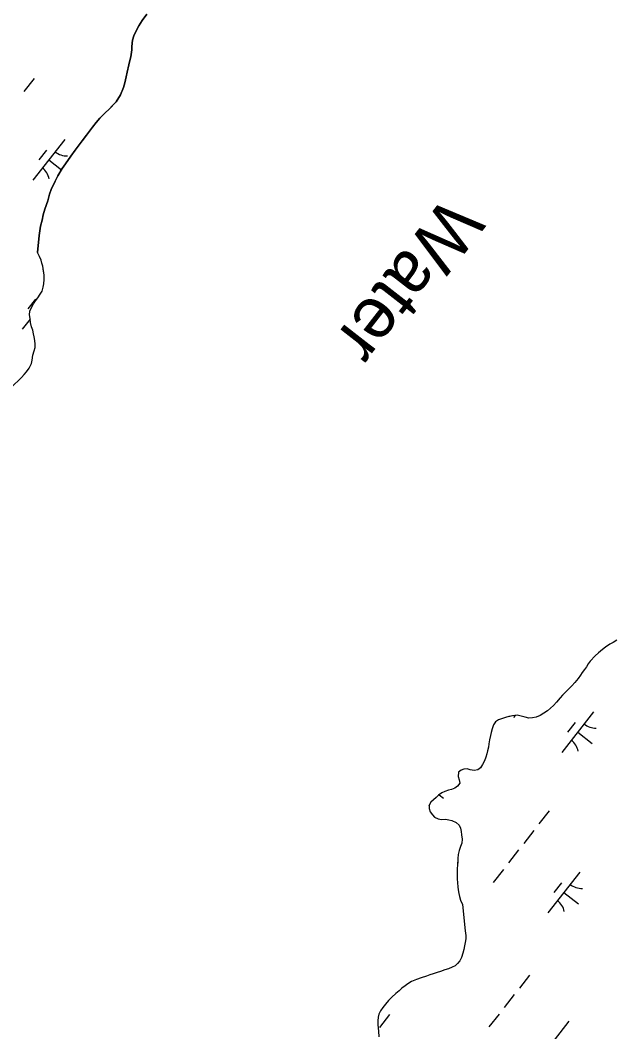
# Model space of a CAD drawing. Extents: x 3896831 to 3918110, y 171006 to 193349.
# Drawn here: x 3911519 to 3912098, y 179895 to 180876 of the extents above; entities that cross this region are included whole.
import ezdxf

# ---------------------------------------------------------------- set-up
doc = ezdxf.new("R2010")
doc.units = 0
for name, color, linetype in [('V-RIVR-IDEN', 7, 'Continuous'), ('V-TOPO-SHOR', 7, 'Continuous'), ('V-WETL-SWMP', 7, 'Continuous')]:
    doc.layers.add(name, color=color, linetype=linetype)

msp = doc.modelspace()

# ---------------------------------------------------------------- linework, layer by layer
at = {"layer": 'V-TOPO-SHOR'}
for points in [[(3911642.32, 180881.66), (3911637.81, 180875.42), (3911634.59, 180870.5), (3911631.06, 180864.27)], [(3911631.06, 180864.27), (3911629.46, 180860.68), (3911628.2, 180856.42), (3911627.6, 180850.22), (3911627.63, 180846.96), (3911626.7, 180840.43), (3911625.76, 180836.84), (3911624.82, 180832.59), (3911623.25, 180825.4), (3911621.99, 180820.83), (3911620.73, 180814.95), (3911619.47, 180810.7), (3911616.6, 180803.5), (3911612.42, 180796.61), (3911609.19, 180793.32), (3911605.31, 180789.38), (3911602.07, 180786.41), (3911596.58, 180780.82), (3911593.03, 180776.55), (3911589.48, 180771.96), (3911583.68, 180764.4), (3911579.49, 180758.82), (3911572.72, 180749.63), (3911568.53, 180744.05), (3911563.38, 180736.51), (3911560.16, 180731.92), (3911555.98, 180725.03), (3911553.1, 180719.79), (3911549.25, 180711.6), (3911547.66, 180707.02), (3911546.09, 180700.49), (3911543.23, 180692.64), (3911541.65, 180687.08), (3911540.71, 180681.85), (3911539.13, 180675.97), (3911537.58, 180667.15), (3911536.99, 180660.3), (3911536.1, 180650.83), (3911536.03, 180650.38)], [(3911523.18, 180532.04), (3911525.38, 180534.79), (3911527.99, 180538.47), (3911530.35, 180542.95), (3911530.95, 180546.14), (3911531.72, 180550.92), (3911533.01, 180555.3), (3911533.74, 180558.48), (3911533.81, 180561.68), (3911533.48, 180565.15), (3911532.89, 180568.63), (3911532.29, 180571.58), (3911531.43, 180575.2), (3911530.3, 180578.42), (3911529.45, 180582.57), (3911528.87, 180586.58), (3911528.41, 180590.06), (3911528.62, 180593.52), (3911530.29, 180597.09), (3911532.37, 180600.77), (3911534.3, 180603.8), (3911536.49, 180606.69), (3911538.7, 180610.24), (3911540.49, 180613.01), (3911541.64, 180616.98), (3911542.38, 180620.17), (3911542.47, 180624.43), (3911542.68, 180628.42), (3911541.97, 180632.44), (3911541.14, 180637.12), (3911540.26, 180640.07), (3911539.52, 180643.02), (3911538.14, 180646.65), (3911536.03, 180650.38)], [(3911517.6, 180526.29), (3911520.73, 180529.29), (3911523.18, 180532.04)], [(3912098.29, 180274.6), (3912094.63, 180272.27), (3912091.38, 180270.47), (3912087.31, 180267.61), (3912084.46, 180265.4), (3912080.37, 180262.14), (3912077.37, 180259.4), (3912072.45, 180254.28), (3912070.52, 180251.65), (3912068.72, 180248.74), (3912066.79, 180246.11), (3912064.73, 180243.08), (3912062.94, 180240.57), (3912060.73, 180237.28), (3912057.44, 180233.47), (3912054.42, 180230.06), (3912051.82, 180227.3), (3912048.54, 180224.03), (3912045.67, 180221.15), (3912043.34, 180218.52), (3912039.65, 180214.32), (3912036.77, 180211.3), (3912033.91, 180208.55), (3912030.91, 180205.81), (3912027.25, 180203.61), (3912023.73, 180201.55), (3912020.08, 180199.88), (3912016.45, 180199.02), (3912012.7, 180198.84), (3912009.24, 180199.71), (3912005.39, 180200.86), (3912001.53, 180201.61), (3911997.11, 180201.17), (3911993.34, 180200.32), (3911990.12, 180199.58), (3911986.35, 180198.32), (3911983.52, 180197.31), (3911980.53, 180195.37), (3911978.73, 180192.47), (3911977.18, 180188.35), (3911976.3, 180185.03), (3911975.7, 180181.96), (3911974.81, 180177.84), (3911974.06, 180173.97), (3911973.59, 180170.64), (3911972.85, 180167.31), (3911972.25, 180164.25), (3911971.25, 180160.93), (3911969.84, 180157.48), (3911968.02, 180153.91), (3911966.08, 180150.6), (3911963.23, 180148.79), (3911959.87, 180148.06), (3911956.01, 180148.68), (3911953.09, 180149.67), (3911949.88, 180149.47), (3911947.04, 180148.33), (3911944.46, 180146.38)], [(3911944.46, 180146.38), (3911944.37, 180142.37), (3911945.11, 180139.14), (3911945.98, 180135.91), (3911943.77, 180132.75), (3911941.19, 180130.8), (3911937.82, 180129.67), (3911934.86, 180128.93), (3911931.36, 180127.66), (3911928.52, 180126.39), (3911925.27, 180124.18), (3911922.81, 180121.83), (3911920.49, 180119.74), (3911917.77, 180117.52), (3911916.24, 180114.61), (3911916.17, 180111.13), (3911917.17, 180107.9), (3911919.38, 180105.05), (3911921.47, 180102.73), (3911924.79, 180101.32), (3911928.25, 180100.71), (3911932.13, 180100.76), (3911935.2, 180100.3), (3911938.26, 180099.56), (3911942.36, 180097.74), (3911945.25, 180095), (3911946.39, 180092.04), (3911947.12, 180088.81), (3911947.59, 180085.59), (3911948.04, 180081.57), (3911947.69, 180077.57), (3911946.55, 180074.25), (3911945.27, 180070.53), (3911944.38, 180066.54), (3911943.9, 180062.67), (3911943.83, 180059.59), (3911943.77, 180056.38), (3911943.29, 180053.05), (3911943.23, 180049.84), (3911943.28, 180046.23), (3911943.35, 180043.02), (3911943.54, 180039.27), (3911944.12, 180035.38), (3911944.33, 180032.3), (3911944.79, 180028.81), (3911945.66, 180025.72), (3911946.66, 180022.22), (3911948.44, 180018.04), (3911950.98, 179992.44), (3911951.69, 179988.14), (3911951.75, 179984.93), (3911951.14, 179981.33), (3911950.54, 179978.14), (3911949.8, 179974.54), (3911948.78, 179970.82), (3911947.36, 179966.7), (3911945.82, 179963.52), (3911943.76, 179960.89), (3911941.3, 179958.67), (3911938.6, 179957.26), (3911934.95, 179955.6), (3911931.32, 179954.6), (3911927.01, 179953.22), (3911923.91, 179952.22), (3911920.01, 179950.96), (3911916.65, 179949.96), (3911913.41, 179948.69), (3911908.29, 179946.93), (3911903.71, 179945.29), (3911899.12, 179943.51), (3911895.33, 179941.32), (3911892.75, 179939.37), (3911889.49, 179936.89), (3911886.9, 179934.54), (3911883.89, 179931.66), (3911880.08, 179928.27), (3911876.66, 179924.86), (3911873.65, 179921.45), (3911871.17, 179918.29), (3911868.96, 179914.99), (3911867.43, 179911.81), (3911866.56, 179908.76), (3911866.22, 179905.29), (3911866.41, 179901.8), (3911866.74, 179898.32), (3911867.07, 179895.1), (3911867.37, 179889.88)]]:
    msp.add_lwpolyline(points, dxfattribs=at)
at = {"layer": 'V-WETL-SWMP'}
for p, q in [((3911634.59, 180870.5), (3911637.81, 180875.42)), ((3911637.81, 180875.42), (3911642.32, 180881.66)), ((3911629.46, 180860.68), (3911631.06, 180864.28)), ((3911631.06, 180864.28), (3911634.59, 180870.5)), ((3911627.6, 180850.22), (3911628.2, 180856.42)), ((3911628.2, 180856.42), (3911629.46, 180860.68)), ((3911626.71, 180840.43), (3911627.63, 180846.96)), ((3911627.63, 180846.96), (3911627.6, 180850.22)), ((3911624.82, 180832.59), (3911625.76, 180836.84)), ((3911625.76, 180836.84), (3911626.71, 180840.43)), ((3911621.99, 180820.83), (3911623.25, 180825.4)), ((3911623.25, 180825.4), (3911624.82, 180832.59)), ((3911532.76, 180819.39), (3911522.89, 180806.8)), ((3911619.47, 180810.7), (3911620.73, 180814.95)), ((3911620.73, 180814.95), (3911621.99, 180820.83)), ((3911616.6, 180803.5), (3911619.47, 180810.7)), ((3911605.31, 180789.38), (3911612.42, 180796.61)), ((3911612.42, 180796.61), (3911616.6, 180803.5)), ((3911596.58, 180780.82), (3911602.07, 180786.41)), ((3911602.07, 180786.41), (3911605.31, 180789.38)), ((3911589.48, 180771.96), (3911593.03, 180776.55)), ((3911593.03, 180776.55), (3911596.58, 180780.82)), ((3911579.49, 180758.82), (3911583.68, 180764.4)), ((3911583.68, 180764.4), (3911589.48, 180771.96)), ((3911562.48, 180759.99), (3911531.64, 180720.63)), ((3911572.72, 180749.63), (3911579.49, 180758.82)), ((3911544.69, 180749.79), (3911537.28, 180740.35)), ((3911568.53, 180744.05), (3911572.72, 180749.63)), ((3911547.06, 180740.31), (3911559.39, 180730.64)), ((3911560.16, 180731.92), (3911563.38, 180736.51)), ((3911563.38, 180736.51), (3911568.53, 180744.05)), ((3911555.98, 180725.03), (3911560.16, 180731.92)), ((3911549.25, 180711.6), (3911553.1, 180719.79)), ((3911553.1, 180719.79), (3911555.98, 180725.03)), ((3911546.09, 180700.49), (3911547.67, 180707.02)), ((3911547.67, 180707.02), (3911549.25, 180711.6)), ((3911543.23, 180692.64), (3911546.09, 180700.49)), ((3911540.71, 180681.85), (3911541.65, 180687.08)), ((3911541.65, 180687.08), (3911543.23, 180692.64)), ((3911539.13, 180675.97), (3911540.71, 180681.85)), ((3911536.99, 180660.3), (3911537.58, 180667.15)), ((3911537.58, 180667.15), (3911539.13, 180675.97)), ((3911536.1, 180650.83), (3911536.99, 180660.3)), ((3911536.03, 180650.38), (3911536.1, 180650.83)), ((3911538.14, 180646.65), (3911536.03, 180650.38)), ((3911539.52, 180643.02), (3911538.14, 180646.65)), ((3911540.26, 180640.07), (3911539.52, 180643.02)), ((3911541.13, 180637.12), (3911540.26, 180640.07)), ((3911542.68, 180628.42), (3911541.13, 180637.12)), ((3911542.47, 180624.43), (3911542.68, 180628.42)), ((3911541.64, 180616.98), (3911542.38, 180620.16)), ((3911542.38, 180620.16), (3911542.47, 180624.43)), ((3911536.49, 180606.69), (3911538.7, 180610.24)), ((3911538.7, 180610.24), (3911540.49, 180613.01)), ((3911540.49, 180613.01), (3911541.64, 180616.98)), ((3911534.22, 180605.23), (3911526.81, 180595.79)), ((3911530.29, 180597.09), (3911532.37, 180600.78)), ((3911532.37, 180600.78), (3911534.3, 180603.8)), ((3911534.3, 180603.8), (3911536.49, 180606.69)), ((3911528.41, 180590.06), (3911528.62, 180593.52)), ((3911528.87, 180586.58), (3911528.41, 180590.06)), ((3911528.62, 180593.52), (3911530.29, 180597.09)), ((3911528.95, 180586.01), (3911521.16, 180576.08)), ((3911529.45, 180582.57), (3911528.87, 180586.58)), ((3911530.3, 180578.42), (3911529.45, 180582.57)), ((3911531.43, 180575.2), (3911530.3, 180578.42)), ((3911532.29, 180571.58), (3911531.43, 180575.2)), ((3911532.89, 180568.63), (3911532.29, 180571.58)), ((3911533.48, 180565.15), (3911532.89, 180568.63)), ((3911533.01, 180555.3), (3911533.74, 180558.48)), ((3911533.81, 180561.68), (3911533.48, 180565.15)), ((3911533.74, 180558.48), (3911533.81, 180561.68)), ((3911530.95, 180546.14), (3911531.72, 180550.92)), ((3911531.72, 180550.92), (3911533.01, 180555.3)), ((3911527.99, 180538.47), (3911530.35, 180542.95)), ((3911530.35, 180542.95), (3911530.95, 180546.14)), ((3911510.66, 180519.64), (3911520.73, 180529.29)), ((3911520.73, 180529.29), (3911523.19, 180532.04)), ((3911523.19, 180532.04), (3911525.38, 180534.79)), ((3911525.38, 180534.79), (3911527.99, 180538.47)), ((3912098.29, 180274.6), (3912094.63, 180272.27)), ((3912084.46, 180265.4), (3912080.37, 180262.14)), ((3912087.31, 180267.61), (3912084.46, 180265.4)), ((3912091.38, 180270.47), (3912087.31, 180267.61)), ((3912094.63, 180272.27), (3912091.38, 180270.47)), ((3912072.45, 180254.28), (3912070.52, 180251.65)), ((3912077.37, 180259.4), (3912072.45, 180254.28)), ((3912080.37, 180262.14), (3912077.37, 180259.4)), ((3912066.8, 180246.11), (3912064.73, 180243.08)), ((3912068.72, 180248.74), (3912066.8, 180246.11)), ((3912070.52, 180251.65), (3912068.72, 180248.74)), ((3912060.73, 180237.28), (3912057.44, 180233.47)), ((3912062.93, 180240.57), (3912060.73, 180237.28)), ((3912064.73, 180243.08), (3912062.93, 180240.57)), ((3912051.82, 180227.3), (3912048.54, 180224.03)), ((3912054.42, 180230.06), (3912051.82, 180227.3)), ((3912057.44, 180233.47), (3912054.42, 180230.06)), ((3912043.34, 180218.52), (3912039.64, 180214.32)), ((3912045.67, 180221.15), (3912043.34, 180218.52)), ((3912048.54, 180224.03), (3912045.67, 180221.15)), ((3912030.91, 180205.81), (3912027.25, 180203.61)), ((3912033.91, 180208.55), (3912030.91, 180205.81)), ((3912036.77, 180211.3), (3912033.91, 180208.55)), ((3912039.64, 180214.32), (3912036.77, 180211.3)), ((3911980.53, 180195.37), (3911978.73, 180192.46)), ((3911983.52, 180197.31), (3911980.53, 180195.37)), ((3911986.35, 180198.32), (3911983.52, 180197.31)), ((3911990.12, 180199.58), (3911986.35, 180198.32)), ((3911997.1, 180201.17), (3911990.12, 180199.58)), ((3912001.53, 180201.61), (3911997.1, 180201.17)), ((3911999.55, 180201.42), (3911998, 180199.44)), ((3912005.39, 180200.86), (3912001.53, 180201.61)), ((3912009.24, 180199.71), (3912005.39, 180200.86)), ((3912012.7, 180198.84), (3912009.24, 180199.71)), ((3912016.45, 180199.03), (3912012.7, 180198.84)), ((3912020.08, 180199.88), (3912016.45, 180199.03)), ((3912023.73, 180201.55), (3912020.08, 180199.88)), ((3912027.25, 180203.61), (3912023.73, 180201.55)), ((3912075.68, 180204.99), (3912044.84, 180165.64)), ((3911977.17, 180188.35), (3911976.3, 180185.03)), ((3911978.73, 180192.46), (3911977.17, 180188.35)), ((3912057.89, 180194.8), (3912050.49, 180185.35)), ((3911974.81, 180177.84), (3911974.06, 180173.97)), ((3911975.7, 180181.96), (3911974.81, 180177.84)), ((3911976.3, 180185.03), (3911975.7, 180181.96)), ((3912060.26, 180185.32), (3912074.43, 180174.21)), ((3911972.85, 180167.31), (3911972.25, 180164.25)), ((3911973.59, 180170.64), (3911972.85, 180167.31)), ((3911974.06, 180173.97), (3911973.59, 180170.64)), ((3911969.84, 180157.48), (3911968.02, 180153.91)), ((3911971.25, 180160.93), (3911969.84, 180157.48)), ((3911972.25, 180164.25), (3911971.25, 180160.93)), ((3911944.46, 180146.38), (3911944.37, 180142.37)), ((3911947.04, 180148.33), (3911944.46, 180146.38)), ((3911949.87, 180149.47), (3911947.04, 180148.33)), ((3911953.09, 180149.67), (3911949.87, 180149.47)), ((3911956.01, 180148.68), (3911953.09, 180149.67)), ((3911959.87, 180148.06), (3911956.01, 180148.68)), ((3911963.23, 180148.79), (3911959.87, 180148.06)), ((3911966.08, 180150.6), (3911963.23, 180148.79)), ((3911968.02, 180153.91), (3911966.08, 180150.6)), ((3911944.37, 180142.37), (3911945.11, 180139.14)), ((3911945.11, 180139.14), (3911945.98, 180135.91)), ((3911931.36, 180127.66), (3911928.52, 180126.39)), ((3911934.86, 180128.93), (3911931.36, 180127.66)), ((3911937.82, 180129.67), (3911934.86, 180128.93)), ((3911941.19, 180130.8), (3911937.82, 180129.67)), ((3911943.77, 180132.75), (3911941.19, 180130.8)), ((3911945.98, 180135.91), (3911943.77, 180132.75)), ((3911917.77, 180117.52), (3911916.24, 180114.61)), ((3911920.49, 180119.73), (3911917.77, 180117.52)), ((3911922.81, 180121.83), (3911920.49, 180119.73)), ((3911925.27, 180124.18), (3911922.81, 180121.83)), ((3911928.52, 180126.39), (3911925.27, 180124.18)), ((3911925.85, 180124.58), (3911930.09, 180121.25)), ((3911916.24, 180114.61), (3911916.17, 180111.13)), ((3911916.17, 180111.13), (3911917.17, 180107.9)), ((3911917.17, 180107.9), (3911919.38, 180105.05)), ((3912032.55, 180108.83), (3912022.68, 180096.24)), ((3911919.38, 180105.05), (3911921.47, 180102.73)), ((3911921.47, 180102.73), (3911924.79, 180101.32)), ((3911924.79, 180101.32), (3911928.25, 180100.71)), ((3911928.25, 180100.71), (3911932.13, 180100.76)), ((3911932.13, 180100.76), (3911935.2, 180100.3)), ((3911935.2, 180100.3), (3911938.26, 180099.57)), ((3911938.26, 180099.57), (3911942.36, 180097.74)), ((3911942.36, 180097.74), (3911945.25, 180095)), ((3911945.25, 180095), (3911946.39, 180092.04)), ((3911946.39, 180092.04), (3911947.12, 180088.81)), ((3911947.12, 180088.81), (3911947.59, 180085.59)), ((3912017.74, 180089.94), (3912007.87, 180077.35)), ((3911947.59, 180085.59), (3911948.04, 180081.57)), ((3911948.04, 180081.57), (3911947.69, 180077.57)), ((3911945.27, 180070.53), (3911944.38, 180066.54)), ((3911946.55, 180074.25), (3911945.27, 180070.53)), ((3911947.69, 180077.57), (3911946.55, 180074.25)), ((3912002.94, 180071.05), (3911993.07, 180058.46)), ((3911943.9, 180062.67), (3911943.77, 180056.38)), ((3911944.38, 180066.54), (3911943.9, 180062.67)), ((3911943.29, 180053.05), (3911943.23, 180049.84)), ((3911943.23, 180049.84), (3911943.28, 180046.23)), ((3911943.77, 180056.38), (3911943.29, 180053.05)), ((3911988.13, 180052.16), (3911978.26, 180039.57)), ((3912062.27, 180049.43), (3912031.42, 180010.07)), ((3911943.28, 180046.23), (3911943.35, 180043.02)), ((3911943.35, 180043.02), (3911943.54, 180039.27)), ((3911943.54, 180039.27), (3911944.12, 180035.38)), ((3912044.47, 180039.23), (3912037.07, 180029.79)), ((3911944.12, 180035.38), (3911944.33, 180032.3)), ((3911944.33, 180032.3), (3911944.79, 180028.81)), ((3911944.79, 180028.81), (3911945.66, 180025.72)), ((3912046.84, 180029.75), (3912061.01, 180018.65)), ((3911945.66, 180025.72), (3911946.66, 180022.22)), ((3911946.66, 180022.22), (3911948.44, 180018.04)), ((3911948.44, 180018.04), (3911950.98, 179992.44)), ((3911950.98, 179992.44), (3911951.69, 179988.14)), ((3911951.14, 179981.33), (3911950.54, 179978.14)), ((3911951.75, 179984.93), (3911951.14, 179981.33)), ((3911951.69, 179988.14), (3911951.75, 179984.93)), ((3911948.78, 179970.82), (3911947.36, 179966.7)), ((3911949.8, 179974.54), (3911948.78, 179970.82)), ((3911950.54, 179978.14), (3911949.8, 179974.54)), ((3911943.76, 179960.89), (3911941.3, 179958.67)), ((3911945.82, 179963.52), (3911943.76, 179960.89)), ((3911947.36, 179966.7), (3911945.82, 179963.52)), ((3911920.01, 179950.96), (3911916.65, 179949.96)), ((3911923.92, 179952.22), (3911920.01, 179950.96)), ((3911927.01, 179953.22), (3911923.92, 179952.22)), ((3911931.32, 179954.6), (3911927.01, 179953.22)), ((3911934.95, 179955.59), (3911931.32, 179954.6)), ((3911938.6, 179957.26), (3911934.95, 179955.59)), ((3911941.3, 179958.67), (3911938.6, 179957.26)), ((3911895.33, 179941.32), (3911892.75, 179939.37)), ((3911899.12, 179943.51), (3911895.33, 179941.32)), ((3911903.71, 179945.29), (3911899.12, 179943.51)), ((3911908.29, 179946.93), (3911903.71, 179945.29)), ((3911913.41, 179948.69), (3911908.29, 179946.93)), ((3911916.65, 179949.96), (3911913.41, 179948.69)), ((3912013.59, 179949.68), (3912003.72, 179937.09)), ((3911883.89, 179931.66), (3911880.08, 179928.27)), ((3911886.9, 179934.54), (3911883.89, 179931.66)), ((3911889.49, 179936.89), (3911886.9, 179934.54)), ((3911892.75, 179939.37), (3911889.49, 179936.89)), ((3911998.78, 179930.79), (3911988.91, 179918.2)), ((3911873.65, 179921.45), (3911871.17, 179918.29)), ((3911876.66, 179924.86), (3911873.65, 179921.45)), ((3911880.08, 179928.27), (3911876.66, 179924.86)), ((3911867.43, 179911.81), (3911866.56, 179908.76)), ((3911868.96, 179914.99), (3911867.43, 179911.81)), ((3911877.74, 179911.31), (3911867.87, 179898.72)), ((3911871.17, 179918.29), (3911868.96, 179914.99)), ((3911983.98, 179911.9), (3911974.11, 179899.31)), ((3911866.56, 179908.76), (3911866.22, 179905.29)), ((3911866.22, 179905.29), (3911866.41, 179901.8)), ((3911866.41, 179901.8), (3911866.74, 179898.32)), ((3912051.79, 179904.87), (3912020.95, 179865.52)), ((3911866.74, 179898.32), (3911867.07, 179895.1)), ((3911867.07, 179895.1), (3911867.37, 179889.88))]:
    msp.add_line(p, q, dxfattribs=at)
for centre, start, end in [((3911564.28, 180761.9), 231.14028, 272.68394), ((3911530.21, 180718.42), 11.14028, 52.68394), ((3912077.49, 180206.91), 231.14028, 272.68394), ((3912043.41, 180163.43), 11.14028, 52.68394), ((3911899.07, 180110.47), 11.14028, 13.1509), ((3912064.07, 180051.34), 231.14028, 272.68394), ((3912029.99, 180007.86), 11.14028, 52.68394)]:
    msp.add_arc(centre, 17.62, start, end, dxfattribs=at)

# ---------------------------------------------------------------- texts
at = {"layer": 'V-RIVR-IDEN'}
msp.add_text('Water', height=50, rotation=232.08429, dxfattribs=at).set_placement((3911932.42, 180707.32))

doc.saveas('drawing.dxf')
